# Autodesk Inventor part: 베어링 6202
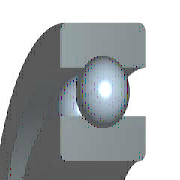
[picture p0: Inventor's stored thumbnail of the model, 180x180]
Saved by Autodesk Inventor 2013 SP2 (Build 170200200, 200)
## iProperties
IsCustomPart: 1
Created: 2015-12
Part Number: 베어링 6202
Material: 강철, 연강
Description: 깊은 그루브 볼 베어링
Document SubType Name: Modeling
Standard: KS B 2023
Designer: mdu
Standards Organization: KS
Language: ko-KR
Size Designation: 6202 - 15 x 35 x 11
Categories: <MemberInstance><Categories><Category DisplayName="샤프트 부품" InternalName="7f7aeb1f-a693-4053-b835-cee3144e0d98" Mnemonic="SHFT"><Category DisplayName="베어링" Inter
Density: 7.86 g/cm^3
Mass: 45.8725 g
Surface Area: 51.5584 cm^2
Volume: 5.83619 cm^3
Author: mdu
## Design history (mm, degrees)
sketch "스케치" dims "d0" = 5.2 (= -0.26 x WD + 0.26 x BD)
  geometry: L1 (2.9, 12.5)-(8.1, 12.5); L2 (5.5, 12.5)-(5.5, 9.9); L3 (5.5, 12.5)-(5.5, 15.1); L4 (3.568, 10.76)-(0, 10.76); L5 (0, 7.5)-(11, 7.5); L6 (3.568, 14.24)-(0, 14.24); L7 (0, 17.5)-(11, 17.5); L8 (11, 7.5)-(11, 10.76); L9 (7.432, 10.76)-(11, 10.76); L10 (7.432, 14.24)-(11, 14.24); L11 (11, 17.5)-(11, 14.24); L12 (-1.4, 0)-(8.4, 0) reference; L13 (0, -0.3)-(0, 5.3) reference
  constraints: 22 end point, 4 point on line, 2 collinear, 2 perpendicular, 2 symmetric about line, 1 midpoint, 1 parallel, 14 other
  dimensions: "d9" = 15 diameter of L5 L12 (= WD); "d11" = 35 diameter of L7 L12 (= BD); "d12" = 11 distance between parallel lines of L8 L13 (= KB); "d13" = 21.52 diameter of L9 L12 (= 0.326 x BD + 0.674 x WD)
revolve "본체" stored, may be unused: angle "d6" = 90 deg
revolve "볼" stored, may be unused: angle "d7" = 90 deg
pattern_circular "IDS_ARRAYBALL[SIMPL:T]" dims angle "d3" = 360 deg
body "Solid1"
fillet "모깎기1" dims "d1" = 0.6 (= KRS)
other parameters: "WD" = 15 [user parameter; used in 5 equation terms], "BD" = 35 [user parameter; used in 5 equation terms], "KB" = 11 [user parameter; used in 1 equation term], "KRS" = 0.6 [user parameter; used in 1 equation term], "d4" = 0, "d5" = 0, "d8" = 0, "d14" = 0, "d15" = 0, "BBA" = 0 [user parameter], "BC0" = 3750000 [user parameter], "BC" = 7800000 [user parameter], "BR" = 17.5 (= 0.5 x BD) [user parameter], "WR" = 7.5 (= 0.5 x WD) [user parameter]
